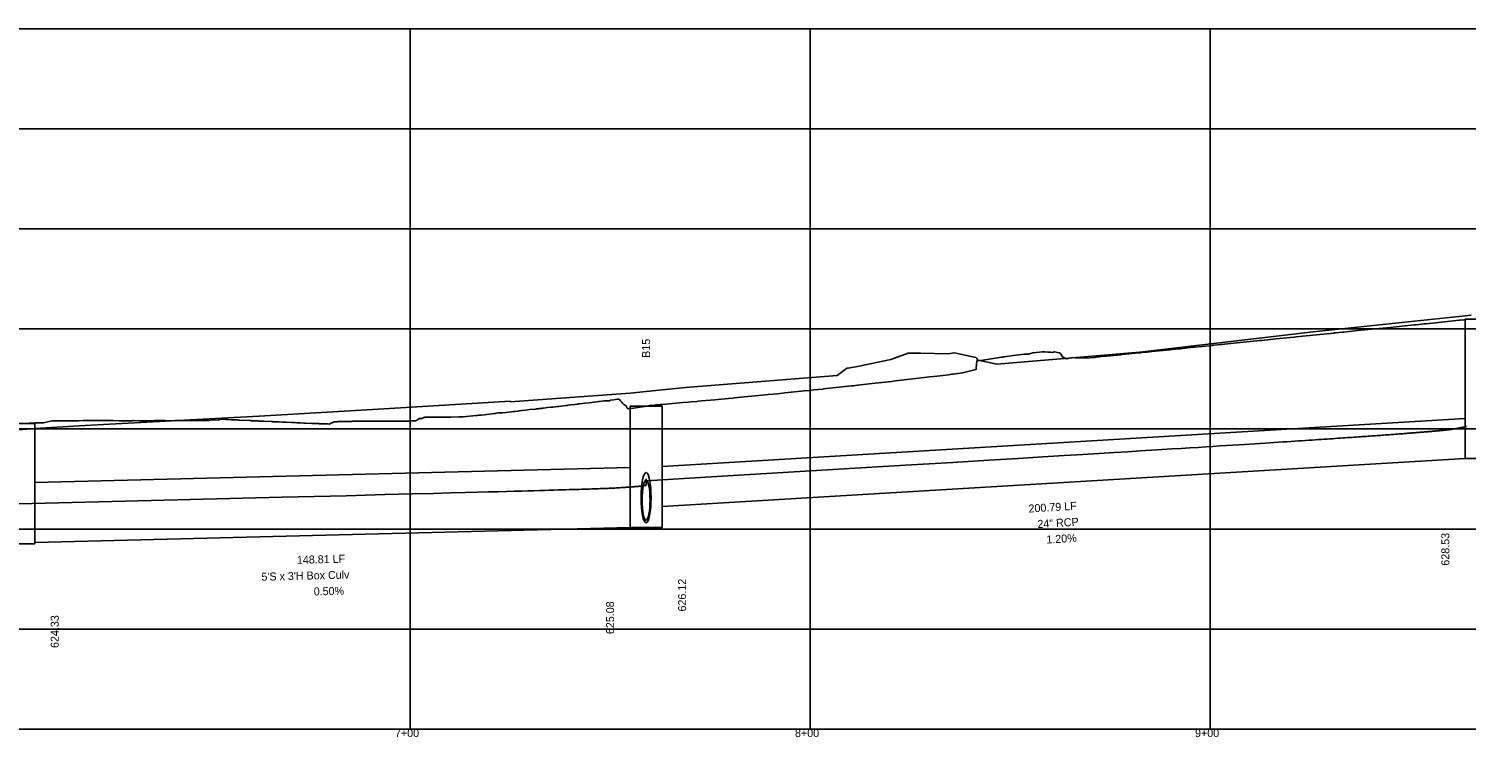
# Model space of a CAD drawing. Extents: x 2253035 to 2279930, y 13774972 to 13793443.
# Drawn here: x 2260631.1 to 2260990.4, y 13791296.5 to 13791473.6 of the extents above; entities that cross this region are included whole.
import ezdxf

# ---------------------------------------------------------------- set-up
doc = ezdxf.new("R2010")
doc.units = 0
for name, color, linetype in [('Default', 7, 'Continuous'), ('E_Utility_ATT_HH', 7, 'Continuous'), ('E_Utility_ATT_PR_PVC', 7, 'Continuous'), ('E_Utillity_Water_Water Line_12in', 7, 'Continuous'), ('E_Utillity_Water_Water Line_1in', 7, 'Continuous'), ('E_Utillity_Water_Water Line_4in', 7, 'Continuous'), ('E_Utillity_Water_Water Line_8in', 7, 'Continuous')]:
    doc.layers.add(name, color=color, linetype=linetype)

msp = doc.modelspace()

# ---------------------------------------------------------------- linework, layer by layer
at = {"layer": 'Default'}
for p, q in [((2260726.46, 13791298.56), (2260726.46, 13791473.56)), ((2260826.46, 13791298.56), (2260826.46, 13791473.56)), ((2260926.46, 13791298.56), (2260926.46, 13791473.56)), ((2260026.46, 13791448.56), (2261320.64, 13791448.56)), ((2260026.46, 13791423.56), (2261320.64, 13791423.56)), ((2260026.46, 13791398.56), (2261320.64, 13791398.56)), ((2260026.46, 13791373.56), (2261320.64, 13791373.56)), ((2260026.46, 13791348.56), (2261320.64, 13791348.56)), ((2260026.46, 13791323.56), (2261320.64, 13791323.56))]:
    msp.add_line(p, q, dxfattribs=at)
msp.add_lwpolyline([(2260026.46, 13791298.56), (2260026.46, 13791473.56), (2261320.64, 13791473.56), (2261320.64, 13791298.56)], close=True, dxfattribs=at)
at = {"layer": 'E_Utility_ATT_PR_PVC'}
msp.add_line((2260785.42, 13791361.13), (2260785.42, 13791360.59), dxfattribs=at)
for points in [[(2260785.42, 13791360.59), (2260804.4, 13791361.73), (2260833.5, 13791363.48), (2260850.29, 13791364.5), (2260862.07, 13791365.21), (2260871.11, 13791365.76), (2260878.45, 13791366.2), (2260884.61, 13791366.58), (2260889.92, 13791366.9), (2260894.57, 13791367.18), (2260898.71, 13791367.44), (2260902.44, 13791367.67), (2260905.82, 13791367.87), (2260908.92, 13791368.07), (2260911.78, 13791368.24), (2260914.42, 13791368.41), (2260916.88, 13791368.56), (2260919.19, 13791368.7), (2260921.35, 13791368.84), (2260923.39, 13791368.96), (2260925.31, 13791369.08), (2260927.13, 13791369.2), (2260928.86, 13791369.31), (2260930.5, 13791369.41), (2260932.07, 13791369.51), (2260933.57, 13791369.6), (2260935, 13791369.69), (2260936.37, 13791369.78), (2260937.69, 13791369.87), (2260938.95, 13791369.95), (2260940.16, 13791370.02), (2260941.34, 13791370.1), (2260942.46, 13791370.17), (2260943.55, 13791370.24), (2260944.6, 13791370.31), (2260945.62, 13791370.38), (2260946.6, 13791370.44), (2260947.55, 13791370.5), (2260948.47, 13791370.56), (2260949.37, 13791370.62), (2260950.24, 13791370.68), (2260951.08, 13791370.73), (2260951.9, 13791370.79), (2260952.69, 13791370.84), (2260953.46, 13791370.89), (2260954.22, 13791370.94), (2260954.95, 13791370.99), (2260955.66, 13791371.04), (2260956.36, 13791371.09), (2260957.03, 13791371.13), (2260957.69, 13791371.18), (2260958.34, 13791371.22), (2260958.97, 13791371.26), (2260959.58, 13791371.3), (2260960.18, 13791371.35), (2260960.76, 13791371.39), (2260961.34, 13791371.42), (2260961.89, 13791371.46), (2260962.44, 13791371.5), (2260962.98, 13791371.54), (2260963.5, 13791371.57), (2260964.01, 13791371.61), (2260964.51, 13791371.65), (2260965, 13791371.68), (2260965.48, 13791371.71), (2260965.95, 13791371.75), (2260966.41, 13791371.78), (2260966.86, 13791371.81), (2260967.31, 13791371.84), (2260967.74, 13791371.87), (2260968.17, 13791371.9), (2260968.58, 13791371.93), (2260968.99, 13791371.96), (2260969.39, 13791371.99), (2260969.79, 13791372.02), (2260970.17, 13791372.05), (2260970.55, 13791372.08), (2260970.92, 13791372.11), (2260971.29, 13791372.13), (2260971.65, 13791372.16), (2260972, 13791372.18), (2260972.35, 13791372.21), (2260972.69, 13791372.24), (2260973.02, 13791372.26), (2260973.35, 13791372.29), (2260973.67, 13791372.31), (2260973.99, 13791372.33), (2260974.3, 13791372.36), (2260974.6, 13791372.38), (2260974.9, 13791372.4), (2260975.2, 13791372.43), (2260975.49, 13791372.45), (2260975.78, 13791372.47), (2260976.06, 13791372.49), (2260976.33, 13791372.51), (2260976.61, 13791372.54), (2260976.87, 13791372.56), (2260977.14, 13791372.58), (2260977.4, 13791372.6), (2260977.65, 13791372.62), (2260977.9, 13791372.64), (2260978.15, 13791372.66), (2260978.39, 13791372.68), (2260978.63, 13791372.7), (2260978.86, 13791372.72), (2260979.09, 13791372.74), (2260979.32, 13791372.75), (2260979.54, 13791372.77), (2260979.76, 13791372.79), (2260979.98, 13791372.81), (2260980.19, 13791372.83), (2260980.4, 13791372.84), (2260980.61, 13791372.86), (2260980.82, 13791372.88), (2260981.02, 13791372.9), (2260981.21, 13791372.91), (2260981.41, 13791372.93), (2260981.6, 13791372.95), (2260981.79, 13791372.96), (2260981.97, 13791372.98), (2260982.16, 13791372.99), (2260982.34, 13791373.01), (2260982.51, 13791373.03), (2260982.69, 13791373.04), (2260982.86, 13791373.06), (2260983.03, 13791373.07), (2260983.19, 13791373.09), (2260983.36, 13791373.1), (2260983.52, 13791373.12), (2260983.68, 13791373.13), (2260983.84, 13791373.14), (2260983.99, 13791373.16), (2260984.14, 13791373.17), (2260984.29, 13791373.19), (2260984.44, 13791373.2), (2260984.58, 13791373.21), (2260984.73, 13791373.23), (2260984.87, 13791373.24), (2260985.01, 13791373.26), (2260985.14, 13791373.27), (2260985.28, 13791373.28), (2260985.41, 13791373.29), (2260985.54, 13791373.31), (2260985.67, 13791373.32), (2260985.79, 13791373.33), (2260985.92, 13791373.34), (2260986.04, 13791373.36), (2260986.16, 13791373.37), (2260986.28, 13791373.39), (2260986.4, 13791373.41), (2260986.51, 13791373.42), (2260986.63, 13791373.44), (2260986.74, 13791373.46), (2260986.85, 13791373.48), (2260986.96, 13791373.5), (2260987.06, 13791373.51), (2260987.17, 13791373.53), (2260987.27, 13791373.55), (2260987.37, 13791373.57), (2260987.47, 13791373.58), (2260987.57, 13791373.6), (2260987.67, 13791373.62), (2260987.76, 13791373.63), (2260987.86, 13791373.65), (2260987.95, 13791373.67), (2260988.04, 13791373.68), (2260988.13, 13791373.7), (2260988.22, 13791373.71), (2260988.3, 13791373.73), (2260988.39, 13791373.74), (2260988.47, 13791373.76), (2260988.55, 13791373.77), (2260988.63, 13791373.79), (2260988.71, 13791373.8), (2260988.79, 13791373.82), (2260988.87, 13791373.83), (2260988.94, 13791373.85), (2260989.02, 13791373.86), (2260989.09, 13791373.87), (2260989.16, 13791373.89), (2260989.23, 13791373.9), (2260989.3, 13791373.91), (2260989.37, 13791373.93), (2260989.43, 13791373.94), (2260989.5, 13791373.95), (2260989.56, 13791373.96), (2260989.63, 13791373.98), (2260989.69, 13791373.99), (2260989.75, 13791374), (2260989.81, 13791374.01), (2260989.87, 13791374.03), (2260989.92, 13791374.04), (2260989.98, 13791374.05), (2260990.04, 13791374.06), (2260990.09, 13791374.07), (2260990.14, 13791374.08), (2260990.19, 13791374.1), (2260990.24, 13791374.11), (2260990.29, 13791374.12), (2260990.34, 13791374.13), (2260990.39, 13791374.14), (2260990.44, 13791374.15), (2260990.48, 13791374.16)], [(2260628.6, 13791354.84), (2260648.65, 13791355.34), (2260694.44, 13791356.49), (2260710.46, 13791356.89), (2260720.1, 13791357.14), (2260726.95, 13791357.32), (2260732.25, 13791357.45), (2260736.55, 13791357.57), (2260740.16, 13791357.66), (2260743.26, 13791357.74), (2260745.97, 13791357.82), (2260748.37, 13791357.88), (2260750.52, 13791357.94), (2260752.47, 13791358), (2260754.24, 13791358.04), (2260755.86, 13791358.09), (2260757.36, 13791358.13), (2260758.74, 13791358.17), (2260760.03, 13791358.21), (2260761.23, 13791358.24), (2260762.36, 13791358.28), (2260763.41, 13791358.31), (2260764.4, 13791358.34), (2260765.34, 13791358.37), (2260766.22, 13791358.39), (2260767.06, 13791358.42), (2260767.85, 13791358.44), (2260768.6, 13791358.47), (2260769.32, 13791358.49), (2260770, 13791358.51), (2260770.65, 13791358.53), (2260771.26, 13791358.55), (2260771.86, 13791358.57), (2260772.42, 13791358.59), (2260772.96, 13791358.61), (2260773.48, 13791358.63), (2260773.98, 13791358.65), (2260774.45, 13791358.66), (2260774.91, 13791358.68), (2260775.35, 13791358.7), (2260775.77, 13791358.71), (2260776.17, 13791358.73), (2260776.56, 13791358.74), (2260776.93, 13791358.76), (2260777.29, 13791358.77), (2260777.64, 13791358.79), (2260777.97, 13791358.81), (2260778.29, 13791358.83), (2260778.6, 13791358.85), (2260778.9, 13791358.87), (2260779.19, 13791358.89), (2260779.46, 13791358.91), (2260779.73, 13791358.93), (2260779.98, 13791358.95), (2260780.23, 13791358.96), (2260780.47, 13791358.98), (2260780.7, 13791359), (2260780.92, 13791359.01), (2260781.13, 13791359.03), (2260781.34, 13791359.04), (2260781.54, 13791359.06), (2260781.73, 13791359.07), (2260781.91, 13791359.09), (2260782.09, 13791359.1), (2260782.26, 13791359.12), (2260782.43, 13791359.13), (2260782.58, 13791359.14), (2260782.74, 13791359.15), (2260782.88, 13791359.17), (2260783.02, 13791359.18), (2260783.16, 13791359.19), (2260783.29, 13791359.2), (2260783.42, 13791359.21), (2260783.54, 13791359.22), (2260783.65, 13791359.24), (2260783.76, 13791359.25), (2260783.87, 13791359.26), (2260783.97, 13791359.27), (2260784.07, 13791359.28), (2260784.16, 13791359.29), (2260784.25, 13791359.3), (2260784.34, 13791359.3), (2260784.42, 13791359.31), (2260784.49, 13791359.32), (2260784.57, 13791359.33), (2260784.64, 13791359.34), (2260784.7, 13791359.35), (2260784.77, 13791359.36), (2260784.83, 13791359.36), (2260784.88, 13791359.37), (2260784.94, 13791359.38), (2260784.99, 13791359.39), (2260785.03, 13791359.39), (2260785.08, 13791359.4), (2260785.12, 13791359.41), (2260785.16, 13791359.42), (2260785.19, 13791359.42), (2260785.22, 13791359.43), (2260785.25, 13791359.44), (2260785.28, 13791359.44), (2260785.3, 13791359.45), (2260785.33, 13791359.45), (2260785.35, 13791359.46), (2260785.36, 13791359.47), (2260785.38, 13791359.47), (2260785.39, 13791359.48), (2260785.4, 13791359.48), (2260785.41, 13791359.49), (2260785.41, 13791359.49), (2260785.42, 13791359.5), (2260785.42, 13791359.5), (2260785.42, 13791361.13)]]:
    msp.add_lwpolyline(points, dxfattribs=at)
at = {"layer": 'E_Utillity_Water_Water Line_12in'}
for points in [[(2260990.21, 13791401.01), (2260993.21, 13791401.01), (2260993.21, 13791366.21), (2260990.21, 13791366.21)], [(2260781.42, 13791379.29), (2260789.42, 13791379.29), (2260789.42, 13791348.93), (2260781.42, 13791348.93)], [(2260624.6, 13791374.89), (2260632.6, 13791374.89), (2260632.6, 13791344.86), (2260624.6, 13791344.86)]]:
    msp.add_lwpolyline(points, close=True, dxfattribs=at)
at = {"layer": 'E_Utillity_Water_Water Line_1in'}
msp.add_lwpolyline([(2260628.6, 13791373.36), (2260632.6, 13791373.68), (2260632.6, 13791373.68), (2260645.23, 13791374.41), (2260651.27, 13791374.77), (2260688.67, 13791376.79), (2260721.29, 13791378.66), (2260751.42, 13791380.54), (2260751.46, 13791380.32), (2260781.42, 13791382.48), (2260781.42, 13791382.48), (2260785.42, 13791382.9), (2260785.42, 13791382.9), (2260789.42, 13791383.33), (2260789.42, 13791383.33), (2260795.27, 13791383.91), (2260833.17, 13791386.92), (2260835.55, 13791388.68), (2260835.61, 13791388.73), (2260835.89, 13791388.74), (2260838.27, 13791389.17), (2260846.59, 13791390.95), (2260850.96, 13791392.51), (2260854.09, 13791392.52), (2260860.87, 13791392.36), (2260862.49, 13791392.57), (2260867.88, 13791391.41), (2260868.08, 13791391.16), (2260868.08, 13791391.15), (2260868.33, 13791390.75), (2260868.34, 13791390.75), (2260868.42, 13791390.73), (2260873.14, 13791389.74), (2260908.81, 13791392.74), (2260952.16, 13791397.82), (2260990.21, 13791401.86), (2260990.21, 13791401.86), (2260991.71, 13791402.03)], dxfattribs=at)
at = {"layer": 'E_Utillity_Water_Water Line_4in'}
for p, q in [((2260789.42, 13791364.16), (2260990.21, 13791376.21)), ((2260789.42, 13791354.16), (2260990.21, 13791366.21)), ((2260632.6, 13791360.21), (2260781.42, 13791363.93)), ((2260632.6, 13791345.21), (2260781.42, 13791348.93))]:
    msp.add_line(p, q, dxfattribs=at)
for centre, major_axis in [((2260785.42, 13791356.39), (0, 6.25)), ((2260785.42, 13791355.78), (0, 5))]:
    msp.add_ellipse(centre, major_axis=major_axis, ratio=0.2, dxfattribs=at)
at = {"layer": 'E_Utillity_Water_Water Line_8in'}
msp.add_lwpolyline([(2260629.85, 13791374.9), (2260631.21, 13791375.03), (2260632.53, 13791375.04), (2260632.6, 13791375.05), (2260632.6, 13791375.05), (2260633.35, 13791375.13), (2260633.42, 13791375.13), (2260633.6, 13791375.13), (2260633.76, 13791375.13), (2260634.79, 13791375.12), (2260636.89, 13791375.56), (2260638.2, 13791375.56), (2260638.37, 13791375.56), (2260638.69, 13791375.56), (2260639.91, 13791375.56), (2260641.16, 13791375.56), (2260643.49, 13791375.56), (2260644.72, 13791375.65), (2260646.6, 13791375.65), (2260646.65, 13791375.65), (2260646.65, 13791375.65), (2260648.71, 13791375.64), (2260649.17, 13791375.64), (2260649.69, 13791375.64), (2260652.2, 13791375.64), (2260653.72, 13791375.63), (2260654.56, 13791375.63), (2260656.93, 13791375.63), (2260657.19, 13791375.64), (2260657.32, 13791375.64), (2260658.6, 13791375.63), (2260658.67, 13791375.63), (2260659.85, 13791375.63), (2260662.03, 13791375.63), (2260662.34, 13791375.64), (2260663.61, 13791375.64), (2260663.8, 13791375.65), (2260665.22, 13791375.64), (2260667.52, 13791375.63), (2260667.75, 13791375.65), (2260667.93, 13791375.65), (2260668.61, 13791375.65), (2260668.8, 13791375.66), (2260669.54, 13791375.66), (2260671.54, 13791375.65), (2260671.89, 13791375.68), (2260673.61, 13791375.67), (2260673.94, 13791375.66), (2260676.1, 13791375.65), (2260676.89, 13791375.82), (2260678.49, 13791375.78), (2260678.55, 13791375.78), (2260678.61, 13791375.81), (2260679.01, 13791376.03), (2260679.26, 13791376.01), (2260679.71, 13791375.99), (2260680.4, 13791375.95), (2260681.03, 13791375.92), (2260681.78, 13791375.88), (2260683.27, 13791375.81), (2260683.55, 13791375.79), (2260683.61, 13791375.79), (2260683.68, 13791375.78), (2260683.81, 13791375.78), (2260686.34, 13791375.65), (2260686.62, 13791375.64), (2260686.76, 13791375.63), (2260688.02, 13791375.57), (2260688.36, 13791375.56), (2260688.6, 13791375.54), (2260688.61, 13791375.54), (2260688.97, 13791375.53), (2260689.03, 13791375.52), (2260689.89, 13791375.48), (2260691.78, 13791375.4), (2260692.03, 13791375.39), (2260692.07, 13791375.38), (2260692.34, 13791375.37), (2260693.61, 13791375.31), (2260694.55, 13791375.27), (2260694.9, 13791375.26), (2260694.92, 13791375.26), (2260695.46, 13791375.23), (2260696.77, 13791375.17), (2260697.61, 13791375.14), (2260698.22, 13791375.11), (2260698.61, 13791375.09), (2260699.06, 13791375.08), (2260699.86, 13791375.04), (2260700.25, 13791375.03), (2260701.88, 13791374.96), (2260702.46, 13791374.94), (2260703, 13791374.91), (2260703.43, 13791374.9), (2260703.61, 13791374.89), (2260703.73, 13791374.88), (2260705.32, 13791374.82), (2260705.8, 13791374.8), (2260706.2, 13791374.79), (2260707.47, 13791375.32), (2260707.49, 13791375.32), (2260707.51, 13791375.33), (2260707.52, 13791375.33), (2260708.21, 13791375.33), (2260708.44, 13791375.4), (2260708.62, 13791375.4), (2260708.63, 13791375.4), (2260709.28, 13791375.4), (2260709.93, 13791375.39), (2260710.19, 13791375.45), (2260710.32, 13791375.44), (2260710.32, 13791375.44), (2260710.32, 13791375.44), (2260710.65, 13791375.44), (2260710.65, 13791375.44), (2260710.65, 13791375.44), (2260711.85, 13791375.44), (2260712.14, 13791375.48), (2260712.4, 13791375.48), (2260713.58, 13791375.48), (2260713.62, 13791375.48), (2260714.73, 13791375.48), (2260714.78, 13791375.48), (2260717.13, 13791375.48), (2260717.37, 13791375.5), (2260717.57, 13791375.5), (2260717.74, 13791375.5), (2260717.87, 13791375.5), (2260717.99, 13791375.5), (2260718.02, 13791375.5), (2260718.05, 13791375.5), (2260718.29, 13791375.5), (2260718.54, 13791375.5), (2260720.38, 13791375.51), (2260720.59, 13791375.53), (2260723.6, 13791375.54), (2260724.08, 13791375.54), (2260726.07, 13791375.54), (2260726.09, 13791375.54), (2260726.28, 13791375.54), (2260726.3, 13791375.55), (2260727.69, 13791375.55), (2260727.83, 13791375.56), (2260728.6, 13791376.12), (2260728.68, 13791376.12), (2260728.7, 13791376.14), (2260729.38, 13791376.16), (2260730.14, 13791376.47), (2260731.27, 13791376.48), (2260732.8, 13791376.49), (2260733.59, 13791376.5), (2260733.62, 13791376.51), (2260735.19, 13791376.52), (2260736.55, 13791376.53), (2260736.65, 13791376.54), (2260738.62, 13791376.55), (2260739.73, 13791376.56), (2260740.41, 13791376.63), (2260740.52, 13791376.64), (2260742.83, 13791376.88), (2260743.31, 13791376.93), (2260743.62, 13791376.97), (2260743.86, 13791376.99), (2260744.21, 13791377.03), (2260745.03, 13791377.12), (2260746.2, 13791377.25), (2260747.7, 13791377.41), (2260747.98, 13791377.54), (2260748.46, 13791377.55), (2260748.62, 13791377.55), (2260748.62, 13791377.55), (2260749.05, 13791377.56), (2260749.45, 13791377.6), (2260749.51, 13791377.61), (2260750.46, 13791377.71), (2260751.74, 13791377.85), (2260752.3, 13791377.92), (2260752.59, 13791377.95), (2260753.43, 13791378.04), (2260753.63, 13791378.06), (2260754.46, 13791378.16), (2260755.28, 13791378.25), (2260756.4, 13791378.38), (2260757.86, 13791378.54), (2260757.89, 13791378.55), (2260757.97, 13791378.56), (2260758.53, 13791378.62), (2260758.63, 13791378.63), (2260759.23, 13791378.7), (2260759.35, 13791378.71), (2260759.36, 13791378.72), (2260759.77, 13791378.76), (2260760.81, 13791378.88), (2260761.61, 13791378.98), (2260762.15, 13791379.04), (2260763.31, 13791379.17), (2260763.63, 13791379.21), (2260763.63, 13791379.21), (2260763.63, 13791379.21), (2260765.46, 13791379.43), (2260765.7, 13791379.46), (2260765.86, 13791379.47), (2260766.55, 13791379.56), (2260766.62, 13791379.57), (2260766.64, 13791379.57), (2260767.57, 13791379.68), (2260768.16, 13791379.75), (2260768.45, 13791379.78), (2260768.63, 13791379.8), (2260769.51, 13791379.91), (2260770.04, 13791379.97), (2260771.16, 13791380.11), (2260771.86, 13791380.2), (2260772.33, 13791380.25), (2260772.53, 13791380.28), (2260773.63, 13791380.41), (2260773.71, 13791380.42), (2260774.33, 13791380.5), (2260774.82, 13791380.56), (2260776.3, 13791380.58), (2260776.52, 13791380.77), (2260777.36, 13791380.87), (2260777.78, 13791380.92), (2260778.17, 13791380.97), (2260778.39, 13791381), (2260778.53, 13791381.02), (2260778.63, 13791381.03), (2260778.67, 13791380.99), (2260778.74, 13791380.91), (2260779.06, 13791380.56), (2260779.35, 13791380.25), (2260779.55, 13791380.03), (2260779.9, 13791379.65), (2260779.99, 13791379.56), (2260780.53, 13791379.29), (2260780.63, 13791378.86), (2260780.91, 13791378.56), (2260781.42, 13791378.66), (2260781.42, 13791378.66), (2260781.66, 13791378.7), (2260785.07, 13791379.19), (2260785.1, 13791379.25), (2260785.27, 13791379.28), (2260785.42, 13791379.29), (2260785.42, 13791379.29), (2260786.88, 13791379.48), (2260786.98, 13791379.45), (2260787.84, 13791379.56), (2260788.95, 13791379.65), (2260789.42, 13791379.69), (2260789.42, 13791379.69), (2260790.35, 13791379.77), (2260794.6, 13791380.14), (2260795.9, 13791380.26), (2260796.71, 13791380.33), (2260798.12, 13791380.45), (2260798.47, 13791380.49), (2260799.25, 13791380.56), (2260802.64, 13791380.87), (2260805.99, 13791381.18), (2260807.07, 13791381.28), (2260807.41, 13791381.31), (2260808.27, 13791381.39), (2260809.97, 13791381.56), (2260812.72, 13791381.82), (2260815.93, 13791382.14), (2260817.17, 13791382.26), (2260818.25, 13791382.37), (2260820.12, 13791382.56), (2260822.51, 13791382.8), (2260824.94, 13791383.05), (2260826.24, 13791383.19), (2260827.37, 13791383.3), (2260829.64, 13791383.54), (2260829.7, 13791383.55), (2260829.77, 13791383.56), (2260836.78, 13791384.31), (2260837.17, 13791384.36), (2260838.24, 13791384.47), (2260838.37, 13791384.49), (2260838.44, 13791384.5), (2260838.98, 13791384.56), (2260842.69, 13791384.97), (2260846.83, 13791385.44), (2260847.15, 13791385.48), (2260847.81, 13791385.56), (2260852.88, 13791386.15), (2260856.31, 13791386.56), (2260858.2, 13791386.78), (2260860.99, 13791387.12), (2260861.87, 13791387.23), (2260862.21, 13791387.27), (2260864.52, 13791387.56), (2260867.85, 13791388.45), (2260867.94, 13791388.49), (2260867.96, 13791388.59), (2260868.04, 13791389.8), (2260868.05, 13791390.06), (2260868.06, 13791390.15), (2260868.09, 13791390.56), (2260869.01, 13791390.69), (2260869.61, 13791390.78), (2260873.25, 13791391.33), (2260874.25, 13791391.48), (2260874.47, 13791391.51), (2260874.48, 13791391.51), (2260874.48, 13791391.51), (2260874.48, 13791391.51), (2260874.54, 13791391.51), (2260874.61, 13791391.51), (2260874.63, 13791391.51), (2260874.85, 13791391.56), (2260877.29, 13791391.89), (2260879.91, 13791392.25), (2260880.14, 13791392.25), (2260880.62, 13791392.24), (2260880.63, 13791392.24), (2260880.68, 13791392.23), (2260880.98, 13791392.22), (2260882.07, 13791392.56), (2260883.75, 13791392.76), (2260884.46, 13791392.85), (2260884.98, 13791392.83), (2260885.1, 13791392.82), (2260885.82, 13791392.78), (2260886.53, 13791392.73), (2260887.05, 13791392.69), (2260887.54, 13791392.84), (2260888.67, 13791392.6), (2260888.69, 13791392.61), (2260888.87, 13791392.56), (2260888.98, 13791392.4), (2260889.07, 13791392.25), (2260889.51, 13791391.6), (2260889.53, 13791391.57), (2260889.54, 13791391.56), (2260889.56, 13791391.54), (2260889.91, 13791391.36), (2260889.93, 13791391.37), (2260890.62, 13791391.04), (2260891.96, 13791391.41), (2260892.59, 13791391.37), (2260893.64, 13791391.31), (2260895.26, 13791391.21), (2260897.42, 13791391.43), (2260897.51, 13791391.44), (2260898.6, 13791391.55), (2260898.66, 13791391.56), (2260898.76, 13791391.58), (2260898.76, 13791391.58), (2260898.76, 13791391.58), (2260898.76, 13791391.58), (2260899.61, 13791391.74), (2260899.64, 13791391.74), (2260899.66, 13791391.74), (2260899.88, 13791391.72), (2260899.9, 13791391.73), (2260900, 13791391.74), (2260900, 13791391.74), (2260900.04, 13791391.75), (2260900.15, 13791391.74), (2260900.38, 13791391.73), (2260900.49, 13791391.74), (2260900.5, 13791391.74), (2260901.42, 13791391.83), (2260902, 13791391.89), (2260902.24, 13791391.92), (2260904.11, 13791392.11), (2260904.46, 13791392.14), (2260908.54, 13791392.56), (2260908.68, 13791392.58), (2260908.69, 13791392.58), (2260908.7, 13791392.58), (2260908.73, 13791392.58), (2260908.82, 13791392.58), (2260908.82, 13791392.58), (2260908.82, 13791392.58), (2260909.22, 13791392.62), (2260909.26, 13791392.63), (2260910.65, 13791392.77), (2260911.86, 13791392.89), (2260916.42, 13791393.36), (2260917.44, 13791393.46), (2260917.45, 13791393.46), (2260917.5, 13791393.47), (2260917.76, 13791393.49), (2260918.38, 13791393.56), (2260918.98, 13791393.62), (2260921.52, 13791393.88), (2260926.33, 13791394.36), (2260926.71, 13791394.4), (2260927, 13791394.43), (2260927.36, 13791394.47), (2260928.22, 13791394.56), (2260929.08, 13791394.64), (2260929.14, 13791394.65), (2260929.24, 13791394.66), (2260933.12, 13791395.05), (2260938.07, 13791395.56), (2260938.68, 13791395.63), (2260938.83, 13791395.63), (2260939.22, 13791395.67), (2260939.31, 13791395.68), (2260942.86, 13791396.04), (2260947.39, 13791396.5), (2260947.53, 13791396.52), (2260947.91, 13791396.56), (2260949.47, 13791396.72), (2260951.24, 13791396.9), (2260957.38, 13791397.52), (2260957.61, 13791397.54), (2260957.75, 13791397.56), (2260959.49, 13791397.73), (2260959.64, 13791397.75), (2260959.87, 13791397.77), (2260963.27, 13791398.12), (2260967.59, 13791398.56), (2260968.68, 13791398.69), (2260968.88, 13791398.69), (2260969.62, 13791398.76), (2260969.8, 13791398.78), (2260972.92, 13791399.1), (2260977.43, 13791399.56), (2260977.66, 13791399.58), (2260977.7, 13791399.58), (2260977.96, 13791399.61), (2260979.96, 13791399.81), (2260980.31, 13791399.85), (2260982.02, 13791400.02), (2260987.27, 13791400.56), (2260988.68, 13791400.72), (2260988.89, 13791400.72), (2260989.88, 13791400.82), (2260990.13, 13791400.85), (2260990.21, 13791400.85), (2260990.21, 13791400.85), (2260990.54, 13791400.89)], dxfattribs=at)

# ---------------------------------------------------------------- texts
at = {"layer": 'Default'}
for s, p in [('7+00', (2260722.65, 13791296.56)), ('8+00', (2260822.65, 13791296.56)), ('9+00', (2260922.65, 13791296.56))]:
    msp.add_text(s, height=2, dxfattribs=at).set_placement(p)
at = {"layer": 'E_Utility_ATT_HH'}
for s, rotation, p in [('B15', 90, (2260786.42, 13791391.32)), ('200.79 LF', 3.4336, (2260881.08, 13791352.66)), ('24" RCP', 3.4336, (2260883.31, 13791348.79)), ('1.20%', 3.4336, (2260885.55, 13791344.91)), ('628.53', 90, (2260986.21, 13791339.4)), ('148.81 LF', 1.4321, (2260698.16, 13791339.85)), ("5'S x 3'H Box Culv", 1.4321, (2260689.3, 13791335.63)), ('0.50%', 1.4321, (2260702.37, 13791331.95)), ('626.12', 90, (2260795.42, 13791327.95)), ('625.08', 90, (2260777.42, 13791322.3)), ('624.33', 90, (2260638.6, 13791318.83))]:
    msp.add_text(s, height=2, rotation=rotation, dxfattribs=at).set_placement(p)

doc.saveas('drawing.dxf')
